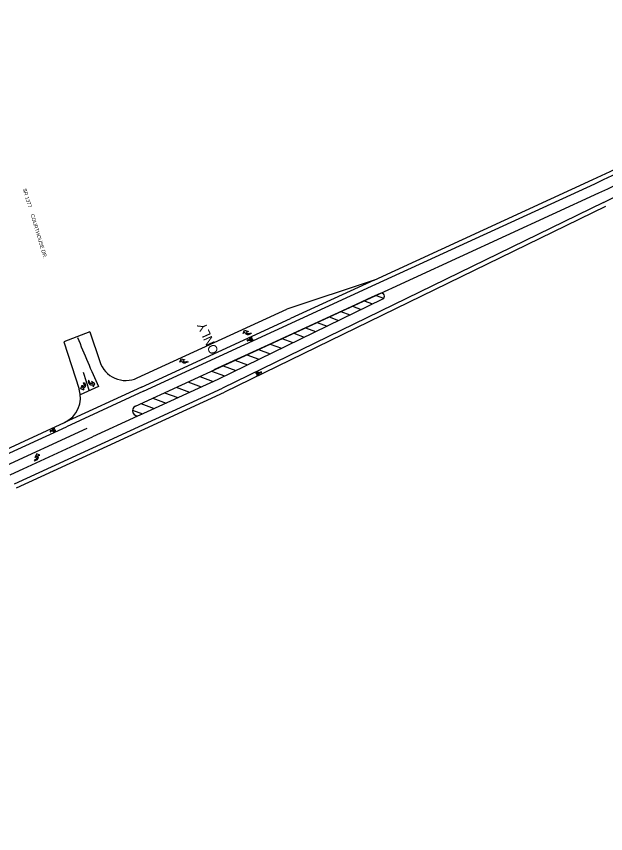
# Model space of a CAD drawing. Extents: x 553958 to 562499, y 493978 to 516388.
# Drawn here: x 559601 to 560245, y 494160 to 495054 of the extents above; entities that cross this region are included whole.
import ezdxf

# ---------------------------------------------------------------- set-up
doc = ezdxf.new("R2010")
doc.units = 0
for name, color, linetype in [('Default', 7, 'Continuous'), ('Old_Level_1', 7, 'Continuous'), ('Prop EOT', 7, 'Continuous'), ('Prop Horizontal Alignment', 7, 'Continuous'), ('Prop Horizontal Alignment Curve and Spiral Data', 7, 'Continuous'), ('Prop Horizontal Alignment Direction Label', 7, 'Continuous'), ('Prop Horizontal Alignment Station Label', 7, 'Continuous'), ('Prop Horizontal Alignment Tick Small', 7, 'Continuous'), ('Prop SS Fill Line', 7, 'Continuous'), ('Sheet North Arrow CELL', 7, 'Continuous'), ('Sheet Plot Border Inside CELL', 7, 'Continuous'), ('Sheet Plot Border Outside CELL', 7, 'Continuous')]:
    doc.layers.add(name, color=color, linetype=linetype)

msp = doc.modelspace()

# ---------------------------------------------------------------- linework, layer by layer
at = {"layer": 'Default'}
for points in [[(559857.64, 494707.87), (559858.01, 494706.94), (559855.61, 494705.98), (559855.16, 494705.82), (559854.8, 494705.75), (559854.39, 494705.72), (559854.02, 494705.75), (559853.72, 494705.82), (559853.31, 494705.96), (559853.01, 494706.11), (559852.68, 494706.3), (559852.31, 494706.58), (559852.08, 494706.82), (559851.8, 494707.17), (559851.51, 494707.68), (559851.21, 494708.43), (559849.38, 494706.97), (559850.71, 494710.56), (559854.96, 494709.39), (559852.68, 494709.02), (559852.93, 494708.4), (559853.09, 494708.06), (559853.31, 494707.77), (559853.52, 494707.57), (559853.84, 494707.33), (559854.11, 494707.18), (559854.51, 494707.05), (559854.93, 494707.02), (559855.34, 494707.03), (559855.86, 494707.15)], [(559857.64, 494707.87), (559858.01, 494706.94), (559855.61, 494705.98), (559855.16, 494705.82), (559854.8, 494705.75), (559854.39, 494705.72), (559854.02, 494705.75), (559853.72, 494705.82), (559853.31, 494705.96), (559853.01, 494706.11), (559852.68, 494706.3), (559852.31, 494706.58), (559852.08, 494706.82), (559851.8, 494707.17), (559851.51, 494707.68), (559851.21, 494708.43), (559849.38, 494706.97), (559850.71, 494710.56), (559854.96, 494709.39), (559852.68, 494709.02), (559852.93, 494708.4), (559853.09, 494708.06), (559853.31, 494707.77), (559853.52, 494707.57), (559853.84, 494707.33), (559854.11, 494707.18), (559854.51, 494707.05), (559854.93, 494707.02), (559855.34, 494707.03), (559855.86, 494707.15)], [(559788.3, 494676.73), (559788.68, 494675.81), (559786.28, 494674.84), (559785.83, 494674.69), (559785.47, 494674.61), (559785.06, 494674.58), (559784.68, 494674.62), (559784.39, 494674.69), (559783.97, 494674.83), (559783.67, 494674.98), (559783.34, 494675.17), (559782.98, 494675.44), (559782.74, 494675.69), (559782.47, 494676.04), (559782.18, 494676.55), (559781.88, 494677.29), (559780.04, 494675.84), (559781.38, 494679.43), (559785.62, 494678.26), (559783.35, 494677.89), (559783.6, 494677.27), (559783.76, 494676.93), (559783.97, 494676.64), (559784.19, 494676.44), (559784.51, 494676.19), (559784.77, 494676.05), (559785.18, 494675.92), (559785.6, 494675.89), (559786, 494675.9), (559786.52, 494676.02)], [(559788.3, 494676.73), (559788.68, 494675.81), (559786.28, 494674.84), (559785.83, 494674.69), (559785.47, 494674.61), (559785.06, 494674.58), (559784.68, 494674.62), (559784.39, 494674.69), (559783.97, 494674.83), (559783.67, 494674.98), (559783.34, 494675.17), (559782.98, 494675.44), (559782.74, 494675.69), (559782.47, 494676.04), (559782.18, 494676.55), (559781.88, 494677.29), (559780.04, 494675.84), (559781.38, 494679.43), (559785.62, 494678.26), (559783.35, 494677.89), (559783.6, 494677.27), (559783.76, 494676.93), (559783.97, 494676.64), (559784.19, 494676.44), (559784.51, 494676.19), (559784.77, 494676.05), (559785.18, 494675.92), (559785.6, 494675.89), (559786, 494675.9), (559786.52, 494676.02)]]:
    msp.add_lwpolyline(points, close=True, dxfattribs=at)
at = {"layer": 'Old_Level_1'}
for p, q in [((559998.92, 494750.79), (559989.83, 494746.61)), ((559998.93, 494750.8), (559998.92, 494750.79)), ((559989.83, 494746.61), (559967.12, 494736.17)), ((559876.27, 494694.37), (559817.22, 494667.21))]:
    msp.add_line(p, q, dxfattribs=at)
msp.add_lwpolyline([(559967.12, 494736.17), (559898.99, 494704.82), (559876.27, 494694.37)], dxfattribs=at)
at = {"layer": 'Prop EOT'}
for p, q in [((559992.23, 494765.33), (559900.84, 494723.28)), ((559738.14, 494648.44), (559653.95, 494609.7)), ((559740.23, 494643.89), (559656.04, 494605.16)), ((559733.74, 494616.69), (559684.49, 494594.03))]:
    msp.add_line(p, q, dxfattribs=at)
at = {"layer": 'Prop Horizontal Alignment'}
for p, q in [((559994.41, 494748.72), (560002.74, 494745.64)), ((559981.57, 494742.81), (559990.63, 494739.46)), ((559955.87, 494730.99), (559965.75, 494727.34)), ((559968.72, 494736.9), (559978.19, 494733.4)), ((559943.02, 494725.08), (559953.31, 494721.28)), ((559917.33, 494713.26), (559928.43, 494709.15)), ((559930.18, 494719.17), (559940.87, 494715.22)), ((559904.48, 494707.35), (559915.98, 494703.09)), ((559878.78, 494695.53), (559891.1, 494690.97)), ((559891.63, 494701.44), (559903.54, 494697.03)), ((559865.94, 494689.62), (559878.66, 494684.91)), ((559840.24, 494677.79), (559853.78, 494672.79)), ((559853.09, 494683.71), (559866.22, 494678.85)), ((559827.39, 494671.88), (559841.34, 494666.72)), ((559801.7, 494660.06), (559816.29, 494654.67)), ((559814.55, 494665.97), (559828.9, 494660.66)), ((559788.85, 494654.15), (559803.44, 494648.76)), ((559763.15, 494642.33), (559777.75, 494636.94)), ((559776, 494648.24), (559790.59, 494642.85)), ((559750.31, 494636.42), (559764.9, 494631.03)), ((559728.2, 494623.27), (559739.2, 494619.2)), ((559737.46, 494630.51), (559752.05, 494625.11))]:
    msp.add_line(p, q, dxfattribs=at)
at = {"layer": 'Prop Horizontal Alignment Curve and Spiral Data'}
for points in [[(559680.68, 494655.71), (559679.73, 494655.39), (559680.54, 494652.94), (559680.72, 494652.49), (559680.89, 494652.17), (559681.14, 494651.84), (559681.4, 494651.58), (559681.65, 494651.39), (559682.02, 494651.17), (559682.33, 494651.04), (559682.69, 494650.91), (559683.13, 494650.8), (559683.47, 494650.78), (559683.92, 494650.8), (559684.49, 494650.9), (559685.26, 494651.16), (559685.33, 494648.81), (559687.21, 494652.15), (559683.58, 494654.64), (559684.76, 494652.66), (559684.13, 494652.45), (559683.77, 494652.36), (559683.41, 494652.34), (559683.11, 494652.37), (559682.72, 494652.46), (559682.44, 494652.56), (559682.08, 494652.79), (559681.78, 494653.09), (559681.53, 494653.41), (559681.29, 494653.89)], [(559680.68, 494655.7), (559679.73, 494655.39), (559680.54, 494652.94), (559680.72, 494652.49), (559680.89, 494652.17), (559681.13, 494651.84), (559681.4, 494651.57), (559681.65, 494651.39), (559682.02, 494651.17), (559682.33, 494651.03), (559682.69, 494650.9), (559683.13, 494650.8), (559683.47, 494650.78), (559683.92, 494650.8), (559684.49, 494650.9), (559685.26, 494651.16), (559685.33, 494648.81), (559687.21, 494652.15), (559683.58, 494654.64), (559684.76, 494652.66), (559684.13, 494652.45), (559683.77, 494652.35), (559683.41, 494652.34), (559683.11, 494652.37), (559682.72, 494652.46), (559682.44, 494652.56), (559682.08, 494652.79), (559681.78, 494653.09), (559681.53, 494653.41), (559681.28, 494653.88)], [(559620.75, 494568.7), (559621.16, 494567.78), (559623.52, 494568.84), (559623.94, 494569.06), (559624.25, 494569.27), (559624.56, 494569.54), (559624.79, 494569.84), (559624.95, 494570.1), (559625.13, 494570.49), (559625.23, 494570.81), (559625.32, 494571.18), (559625.38, 494571.64), (559625.36, 494571.97), (559625.3, 494572.41), (559625.14, 494572.98), (559624.81, 494573.71), (559627.13, 494574.02), (559623.61, 494575.55), (559621.51, 494571.69), (559623.36, 494573.06), (559623.63, 494572.45), (559623.77, 494572.11), (559623.82, 494571.75), (559623.82, 494571.45), (559623.77, 494571.06), (559623.7, 494570.76), (559623.51, 494570.38), (559623.24, 494570.06), (559622.95, 494569.77), (559622.5, 494569.48)], [(559620.75, 494568.7), (559621.16, 494567.78), (559623.52, 494568.84), (559623.94, 494569.06), (559624.25, 494569.27), (559624.56, 494569.54), (559624.79, 494569.84), (559624.95, 494570.1), (559625.13, 494570.49), (559625.23, 494570.81), (559625.32, 494571.18), (559625.38, 494571.64), (559625.36, 494571.98), (559625.3, 494572.42), (559625.14, 494572.98), (559624.81, 494573.71), (559627.13, 494574.03), (559623.61, 494575.55), (559621.51, 494571.69), (559623.36, 494573.06), (559623.63, 494572.45), (559623.77, 494572.11), (559623.82, 494571.75), (559623.82, 494571.45), (559623.77, 494571.06), (559623.7, 494570.76), (559623.51, 494570.38), (559623.24, 494570.06), (559622.95, 494569.77), (559622.5, 494569.48)]]:
    msp.add_lwpolyline(points, close=True, dxfattribs=at)
at = {"layer": 'Prop Horizontal Alignment Direction Label'}
msp.add_lwpolyline([(559674.8, 494653.27), (559675.75, 494653.6), (559676.58, 494651.15), (559676.71, 494650.69), (559676.77, 494650.33), (559676.77, 494649.91), (559676.72, 494649.55), (559676.63, 494649.25), (559676.47, 494648.85), (559676.3, 494648.56), (559676.1, 494648.24), (559675.8, 494647.89), (559675.54, 494647.67), (559675.18, 494647.41), (559674.66, 494647.15), (559673.9, 494646.89), (559675.25, 494644.98), (559671.74, 494646.51), (559673.13, 494650.68), (559673.38, 494648.39), (559674.01, 494648.6), (559674.36, 494648.74), (559674.66, 494648.94), (559674.87, 494649.15), (559675.13, 494649.45), (559675.3, 494649.71), (559675.44, 494650.11), (559675.5, 494650.53), (559675.51, 494650.93), (559675.42, 494651.46)], close=True, dxfattribs=at)
msp.add_lwpolyline([(559674.8, 494653.27), (559675.75, 494653.6), (559676.58, 494651.15), (559676.71, 494650.69), (559676.77, 494650.33), (559676.77, 494649.91), (559676.72, 494649.55), (559676.63, 494649.25), (559676.47, 494648.85), (559676.3, 494648.56), (559676.1, 494648.24), (559675.8, 494647.89), (559675.54, 494647.67), (559675.18, 494647.41), (559674.66, 494647.15), (559673.9, 494646.89), (559675.25, 494644.98), (559671.74, 494646.51), (559673.13, 494650.68), (559673.38, 494648.39), (559674.01, 494648.6), (559674.36, 494648.74), (559674.66, 494648.94), (559674.87, 494649.15), (559675.13, 494649.45), (559675.3, 494649.71), (559675.44, 494650.11), (559675.5, 494650.53), (559675.51, 494650.93), (559675.42, 494651.46)], close=True, dxfattribs=at)
at = {"layer": 'Prop Horizontal Alignment Tick Small'}
for p, q in [((559856.97, 494702.66), (559857.09, 494702.45)), ((559856.97, 494702.66), (559857.09, 494702.45)), ((559854.01, 494699.85), (559853.94, 494699.98)), ((559854.01, 494699.85), (559853.94, 494699.98)), ((559854.48, 494698.99), (559854.4, 494699.13)), ((559854.48, 494698.99), (559854.4, 494699.13)), ((559854.54, 494699.98), (559855.96, 494700.86)), ((559854.78, 494699.75), (559854.54, 494699.98)), ((559856.09, 494699.44), (559854.78, 494699.75)), ((559855.94, 494700.49), (559855.02, 494699.91)), ((559855.02, 494699.91), (559856.36, 494699.59)), ((559856.74, 494699.85), (559855.94, 494700.49)), ((559855.96, 494700.86), (559858.05, 494701.19)), ((559856.36, 494699.59), (559856.09, 494699.44)), ((559858.09, 494700.96), (559856.12, 494700.65)), ((559856.12, 494700.65), (559856.73, 494700.16)), ((559856.73, 494700.16), (559857.22, 494700.58)), ((559857.38, 494700.4), (559856.74, 494699.85)), ((559857.22, 494700.58), (559857.38, 494700.4)), ((559857.48, 494701.73), (559857.59, 494701.52)), ((559857.48, 494701.73), (559857.59, 494701.52)), ((559858.05, 494701.19), (559858.12, 494700.96)), ((559858.14, 494700.51), (559858.25, 494700.3)), ((559858.14, 494700.51), (559858.25, 494700.3)), ((559858.64, 494699.58), (559858.76, 494699.37)), ((559858.64, 494699.58), (559858.76, 494699.37)), ((559864.24, 494664.64), (559864.14, 494664.86)), ((559864.24, 494664.64), (559864.14, 494664.86)), ((559864.69, 494663.68), (559864.59, 494663.9)), ((559864.69, 494663.68), (559864.59, 494663.9)), ((559864.73, 494663), (559864.68, 494663.23)), ((559864.71, 494663.23), (559866.69, 494663.42)), ((559866.84, 494663.2), (559864.73, 494663)), ((559865.27, 494662.42), (559865.17, 494662.64)), ((559865.27, 494662.42), (559865.17, 494662.64)), ((559865.45, 494663.75), (559866.13, 494664.25)), ((559865.6, 494663.56), (559865.45, 494663.75)), ((559866.11, 494663.95), (559865.6, 494663.56)), ((559865.72, 494661.46), (559865.62, 494661.68)), ((559865.72, 494661.46), (559865.62, 494661.68)), ((559866.69, 494663.42), (559866.11, 494663.95)), ((559866.13, 494664.25), (559866.88, 494663.57)), ((559866.52, 494664.49), (559866.8, 494664.62)), ((559867.84, 494664.09), (559866.52, 494664.49)), ((559866.8, 494664.62), (559868.09, 494664.24)), ((559868.31, 494663.99), (559866.84, 494663.2)), ((559866.88, 494663.57), (559867.84, 494664.09)), ((559868.09, 494664.24), (559868.31, 494663.99)), ((559868.43, 494664.98), (559868.5, 494664.84)), ((559868.43, 494664.98), (559868.5, 494664.84)), ((559868.84, 494664.09), (559868.91, 494663.95)), ((559868.84, 494664.09), (559868.91, 494663.95)), ((559638.51, 494600.56), (559638.44, 494600.69)), ((559638.51, 494600.56), (559638.44, 494600.69)), ((559638.98, 494599.7), (559638.9, 494599.84)), ((559638.98, 494599.7), (559638.9, 494599.84)), ((559639.04, 494600.69), (559640.46, 494601.57)), ((559639.28, 494600.46), (559639.04, 494600.69)), ((559640.58, 494600.15), (559639.28, 494600.46)), ((559640.44, 494601.2), (559639.52, 494600.62)), ((559639.52, 494600.62), (559640.86, 494600.3)), ((559641.23, 494600.56), (559640.44, 494601.2)), ((559640.46, 494601.57), (559642.55, 494601.9)), ((559640.86, 494600.3), (559640.58, 494600.15)), ((559642.59, 494601.67), (559640.62, 494601.36)), ((559640.62, 494601.36), (559641.23, 494600.87)), ((559641.23, 494600.87), (559641.72, 494601.29)), ((559641.87, 494601.11), (559641.23, 494600.56)), ((559641.47, 494603.37), (559641.59, 494603.16)), ((559641.47, 494603.37), (559641.59, 494603.16)), ((559641.72, 494601.29), (559641.87, 494601.11)), ((559641.97, 494602.44), (559642.09, 494602.23)), ((559641.97, 494602.44), (559642.09, 494602.23)), ((559642.55, 494601.9), (559642.61, 494601.67)), ((559642.63, 494601.22), (559642.75, 494601.01)), ((559642.63, 494601.22), (559642.75, 494601.01)), ((559643.14, 494600.29), (559643.25, 494600.08)), ((559643.14, 494600.29), (559643.25, 494600.08))]:
    msp.add_line(p, q, dxfattribs=at)
for centre, radius, start, end in [((559854.21, 494699.49), 0.563, 118.39939, 298.39939), ((559854.21, 494699.49), 0.563, 118.39939, 298.39939), ((559854.21, 494699.49), 0.41, 298.39939, 118.39939), ((559868.67, 494664.46), 0.41, 114.91872, 294.91872), ((559868.67, 494664.46), 0.563, 294.91872, 114.91872), ((559868.67, 494664.46), 0.563, 294.91872, 114.91872), ((559638.71, 494600.2), 0.563, 118.39939, 298.39939), ((559638.71, 494600.2), 0.563, 118.39939, 298.39939), ((559638.71, 494600.2), 0.41, 298.39939, 118.39939)]:
    msp.add_arc(centre, radius, start, end, dxfattribs=at)
for centre, major_axis, ratio, start_param, end_param in [((559857.28, 494702.09), (1.31, 0.71), 0.435841, 1.570796, 4.712389), ((559857.28, 494702.09), (1.1, 0.6), 0.325967, 1.570796, 4.712389), ((559857.28, 494702.09), (1.31, 0.71), 0.435841, 4.712389, 7.853982), ((559857.28, 494702.09), (1.1, 0.6), 0.325967, 4.712389, 7.853982), ((559858.45, 494699.94), (1.31, 0.71), 0.435841, 1.570796, 4.712389), ((559858.45, 494699.94), (1.1, 0.6), 0.325967, 1.570796, 4.712389), ((559858.45, 494699.94), (1.31, 0.71), 0.435841, 4.712389, 7.853982), ((559858.45, 494699.94), (1.1, 0.6), 0.325967, 4.712389, 7.853982), ((559864.41, 494664.27), (-1.36, -0.63), 0.435841, 4.712389, 7.853982), ((559864.41, 494664.27), (-1.13, -0.53), 0.325967, 4.712389, 7.853982), ((559865.44, 494662.05), (-1.36, -0.63), 0.435841, 4.712389, 7.853982), ((559864.41, 494664.27), (-1.36, -0.63), 0.435841, 1.570796, 4.712389), ((559865.44, 494662.05), (-1.13, -0.53), 0.325967, 4.712389, 7.853982), ((559864.41, 494664.27), (-1.13, -0.53), 0.325967, 1.570796, 4.712389), ((559865.44, 494662.05), (-1.36, -0.63), 0.435841, 1.570796, 4.712389), ((559865.44, 494662.05), (-1.13, -0.53), 0.325967, 1.570796, 4.712389), ((559641.78, 494602.8), (1.31, 0.71), 0.435841, 1.570796, 4.712389), ((559641.78, 494602.8), (1.1, 0.6), 0.325967, 1.570796, 4.712389), ((559642.94, 494600.65), (1.31, 0.71), 0.435841, 1.570796, 4.712389), ((559641.78, 494602.8), (1.31, 0.71), 0.435841, 4.712389, 7.853982), ((559641.78, 494602.8), (1.1, 0.6), 0.325967, 4.712389, 7.853982), ((559642.94, 494600.65), (1.1, 0.6), 0.325967, 1.570796, 4.712389), ((559642.94, 494600.65), (1.31, 0.71), 0.435841, 4.712389, 7.853982), ((559642.94, 494600.65), (1.1, 0.6), 0.325967, 4.712389, 7.853982)]:
    msp.add_ellipse(centre, major_axis=major_axis, ratio=ratio, start_param=start_param, end_param=end_param, dxfattribs=at)
at = {"layer": 'Prop SS Fill Line'}
for p, q in [((559992.23, 494765.33), (560231.34, 494875.33)), ((560245.33, 494845.77), (559828.67, 494642.75)), ((559992.23, 494765.33), (559896.79, 494733.53)), ((559733.55, 494658.43), (559896.79, 494733.53)), ((559681.75, 494708.87), (559653.05, 494697.8)), ((559681.75, 494708.87), (559692.52, 494676.27)), ((559653.05, 494697.8), (559669.92, 494646.3)), ((559700.44, 494583.76), (559828.67, 494642.75)), ((558708.86, 494174.92), (559653.95, 494609.7)), ((559601.39, 494538.19), (559700.44, 494583.76))]:
    msp.add_line(p, q, dxfattribs=at)
for centre, radius, start, end in [((559707.24, 496014.56), 1254, 294.70456, 309.98225), ((559721.01, 494685.68), 30, 198.28728, 294.70456), ((559641.41, 494636.96), 30, 294.70456, 18.14161)]:
    msp.add_arc(centre, radius, start, end, dxfattribs=at)
at = {"layer": 'Sheet North Arrow CELL'}
msp.add_line((559691.18, 494648.94), (559671.26, 494640), dxfattribs=at)
at = {"layer": 'Sheet Plot Border Inside CELL'}
for p, q in [((559992.23, 494765.33), (560231.34, 494875.33)), ((559994.32, 494760.79), (560233.43, 494870.79)), ((560243.14, 494850.26), (559826.48, 494647.25)), ((560245.33, 494845.77), (559828.67, 494642.75)), ((559992.23, 494765.33), (559896.79, 494733.53)), ((559740.23, 494643.89), (559994.32, 494760.79)), ((559733.55, 494658.43), (559896.79, 494733.53)), ((559738.14, 494648.44), (559900.84, 494723.28)), ((559681.75, 494708.87), (559692.52, 494676.27)), ((559653.05, 494697.8), (559669.92, 494646.3)), ((559674.44, 494664.61), (559681.06, 494644.4)), ((559700.44, 494583.76), (559828.67, 494642.75)), ((559753.61, 494613.72), (559826.53, 494647.27)), ((559698.35, 494588.3), (559753.61, 494613.72)), ((558708.86, 494174.92), (559653.95, 494609.7)), ((558710.95, 494170.38), (559656.04, 494605.16)), ((559594.7, 494552.73), (559684.49, 494594.03)), ((559599.3, 494542.73), (559698.35, 494588.3)), ((559601.39, 494538.19), (559700.44, 494583.76))]:
    msp.add_line(p, q, dxfattribs=at)
for centre, radius, start, end in [((559707.24, 496014.56), 1254, 294.70456, 309.98225), ((559707.24, 496014.56), 1259, 294.70456, 309.98225), ((559681.1, 496003.51), 1282.91, 295.98242, 297.41721), ((559721.01, 494685.68), 30, 198.28728, 294.70456), ((559641.41, 494636.96), 30, 294.70456, 18.14161)]:
    msp.add_arc(centre, radius, start, end, dxfattribs=at)
at = {"layer": 'Sheet Plot Border Outside CELL'}
for p, q in [((559731.38, 494627.71), (560238.03, 494860.79)), ((559735.97, 494617.72), (559821.82, 494657.21)), ((558715.55, 494160.38), (559678.69, 494603.47))]:
    msp.add_line(p, q, dxfattribs=at)
msp.add_lwpolyline([(559821.82, 494657.21), (560001.66, 494744.84), (560001.79, 494744.9)], dxfattribs=at)
for centre, radius, start, end in [((559707.24, 496014.56), 1270, 294.70456, 309.98225), ((560000.29, 494747.81), 3.28, 297.26371, 114.51598), ((560507.69, 495027.51), 900, 201.14535, 204.87423), ((559733.67, 494622.71), 5.5, 114.70456, 294.70456)]:
    msp.add_arc(centre, radius, start, end, dxfattribs=at)

# ---------------------------------------------------------------- texts
at = {"layer": 'Default'}
msp.add_text('SR 1377     COURTHOUSE DR.', height=4, rotation=286.85, dxfattribs=at).set_placement((559608.28, 494864.82))
at = {"layer": 'Prop Horizontal Alignment Station Label'}
msp.add_text('ONLY', height=10, rotation=114.32766, dxfattribs=at).set_placement((559822.64, 494687.15))

doc.saveas('drawing.dxf')
